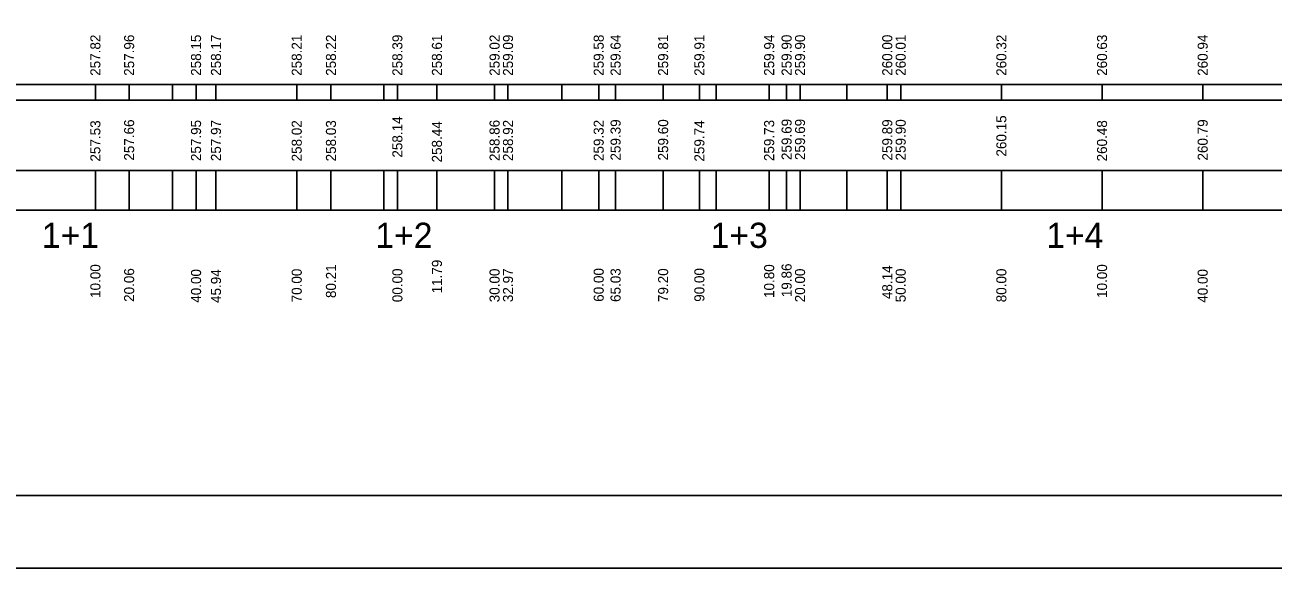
# Model space of a CAD drawing. Extents: x -550605 to -538780, y -1102367 to -1093705.
# Drawn here: x -540305.8 to -539933.8, y -1097677.3 to -1097515.5 of the extents above; entities that cross this region are included whole.
import ezdxf

# ---------------------------------------------------------------- set-up
doc = ezdxf.new("R2010")
doc.units = 0
for name, color, linetype in [('PP - kóty', 7, 'Continuous'), ('PP - popis', 7, 'Continuous'), ('Vrstva 57 - Ohrada pro tisk', 7, 'Continuous')]:
    doc.layers.add(name, color=color, linetype=linetype)

msp = doc.modelspace()

# ---------------------------------------------------------------- linework, layer by layer
at = {"layer": 'PP - popis'}
for p, q in [((-540261.8, -1097533.29), (-540261.8, -1097537.91)), ((-540261.8, -1097533.29), (-540261.8, -1097537.91)), ((-540198.8, -1097533.29), (-540198.8, -1097537.91)), ((-540198.8, -1097533.29), (-540198.8, -1097537.91)), ((-540145.8, -1097533.29), (-540145.8, -1097537.91)), ((-540145.8, -1097533.29), (-540145.8, -1097537.91)), ((-540099.8, -1097533.29), (-540099.8, -1097537.91)), ((-540099.8, -1097533.29), (-540099.8, -1097537.91)), ((-540060.8, -1097533.29), (-540060.8, -1097537.91)), ((-540060.8, -1097533.29), (-540060.8, -1097537.91)), ((-540261.8, -1097558.89), (-540261.8, -1097570.66)), ((-540261.8, -1097558.89), (-540261.8, -1097570.66)), ((-540198.8, -1097558.89), (-540198.8, -1097570.66)), ((-540198.8, -1097558.89), (-540198.8, -1097570.66)), ((-540145.8, -1097558.89), (-540145.8, -1097570.66)), ((-540145.8, -1097558.89), (-540145.8, -1097570.66)), ((-540099.8, -1097558.89), (-540099.8, -1097570.66)), ((-540099.8, -1097558.89), (-540099.8, -1097570.66)), ((-540060.8, -1097558.89), (-540060.8, -1097570.66)), ((-540060.8, -1097558.89), (-540060.8, -1097570.66)), ((-541394.8, -1097570.66), (-539200.8, -1097570.66))]:
    msp.add_line(p, q, dxfattribs=at)
for points in [[(-540284.8, -1097533.29), (-540284.8, -1097537.91)], [(-540274.74, -1097533.29), (-540274.74, -1097537.91)], [(-540254.8, -1097533.29), (-540254.8, -1097537.91)], [(-540248.86, -1097533.29), (-540248.86, -1097537.91)], [(-540224.8, -1097533.29), (-540224.8, -1097537.91)], [(-540214.59, -1097533.29), (-540214.59, -1097537.91)], [(-540194.8, -1097533.29), (-540194.8, -1097537.91)], [(-540183.01, -1097533.29), (-540183.01, -1097537.91)], [(-540165.83, -1097533.29), (-540165.83, -1097537.91)], [(-540161.83, -1097533.29), (-540161.83, -1097537.91)], [(-540134.8, -1097533.29), (-540134.8, -1097537.91)], [(-540129.77, -1097533.29), (-540129.77, -1097537.91)], [(-540115.6, -1097533.29), (-540115.6, -1097537.91)], [(-540104.8, -1097533.29), (-540104.8, -1097537.91)], [(-540084, -1097533.29), (-540084, -1097537.91)], [(-540078.8, -1097533.29), (-540078.8, -1097537.91)], [(-540074.8, -1097533.29), (-540074.8, -1097537.91)], [(-540048.8, -1097533.29), (-540048.8, -1097537.91)], [(-540044.8, -1097533.29), (-540044.8, -1097537.91)], [(-540014.8, -1097533.29), (-540014.8, -1097537.91)], [(-539984.8, -1097533.29), (-539984.8, -1097537.91)], [(-539954.8, -1097533.29), (-539954.8, -1097537.91)], [(-540284.8, -1097558.89), (-540284.8, -1097570.66)], [(-540274.74, -1097558.89), (-540274.74, -1097570.66)], [(-540254.8, -1097558.89), (-540254.8, -1097570.66)], [(-540248.86, -1097558.89), (-540248.86, -1097570.66)], [(-540224.8, -1097558.89), (-540224.8, -1097570.66)], [(-540214.59, -1097558.89), (-540214.59, -1097570.66)], [(-540194.8, -1097558.89), (-540194.8, -1097570.66)], [(-540183.01, -1097558.89), (-540183.01, -1097570.66)], [(-540165.83, -1097558.89), (-540165.83, -1097570.66)], [(-540161.83, -1097558.89), (-540161.83, -1097570.66)], [(-540134.8, -1097558.89), (-540134.8, -1097570.66)], [(-540129.77, -1097558.89), (-540129.77, -1097570.66)], [(-540115.6, -1097558.89), (-540115.6, -1097570.66)], [(-540104.8, -1097558.89), (-540104.8, -1097570.66)], [(-540084, -1097558.89), (-540084, -1097570.66)], [(-540078.8, -1097558.89), (-540078.8, -1097570.66)], [(-540074.8, -1097558.89), (-540074.8, -1097570.66)], [(-540048.8, -1097558.89), (-540048.8, -1097570.66)], [(-540044.8, -1097558.89), (-540044.8, -1097570.66)], [(-540014.8, -1097558.89), (-540014.8, -1097570.66)], [(-539984.8, -1097558.89), (-539984.8, -1097570.66)], [(-539954.8, -1097558.89), (-539954.8, -1097570.66)], [(-541394.8, -1097655.66), (-541347.44, -1097655.66), (-541347.44, -1097667.66), (-541325.3, -1097667.66), (-541325.3, -1097655.66), (-541196.07, -1097655.66), (-541196.07, -1097667.66), (-541142.23, -1097667.66), (-541142.23, -1097655.66), (-540615.98, -1097655.66), (-540615.98, -1097643.66), (-540580.64, -1097643.66), (-540580.64, -1097655.66), (-540387.05, -1097655.66), (-540387.05, -1097643.66), (-540360.85, -1097643.66), (-540360.85, -1097655.66), (-539200.59, -1097655.66)]]:
    msp.add_lwpolyline(points, dxfattribs=at)
at = {"layer": 'Vrstva 57 - Ohrada pro tisk'}
for points in [[(-541634.97, -1097677.25), (-538779.82, -1097677.25), (-538779.81, -1097107.25), (-541634.97, -1097107.25)], [(-541392.34, -1097533.29), (-539148.29, -1097533.29), (-539148.29, -1097512.53), (-541392.34, -1097512.53)], [(-541392.09, -1097558.89), (-539148.83, -1097558.89), (-539148.83, -1097537.91), (-541392.09, -1097537.91)]]:
    msp.add_lwpolyline(points, close=True, dxfattribs=at)

# ---------------------------------------------------------------- texts
at = {"layer": 'PP - kóty'}
for s, p in [('257.82', (-540283.3, -1097530.66)), ('257.96', (-540273.24, -1097530.66)), ('258.15', (-540253.3, -1097530.66)), ('258.17', (-540247.36, -1097530.66)), ('258.21', (-540223.3, -1097530.66)), ('258.22', (-540213.09, -1097530.66)), ('258.39', (-540193.3, -1097530.66)), ('258.61', (-540181.51, -1097530.66)), ('259.02', (-540164.33, -1097530.66)), ('259.09', (-540160.33, -1097530.66)), ('259.58', (-540133.3, -1097530.66)), ('259.64', (-540128.27, -1097530.66)), ('259.81', (-540114.1, -1097530.66)), ('259.91', (-540103.3, -1097530.66)), ('259.94', (-540082.5, -1097530.66)), ('259.90', (-540077.3, -1097530.66)), ('259.90', (-540073.3, -1097530.66)), ('260.00', (-540047.3, -1097530.66)), ('260.01', (-540043.3, -1097530.66)), ('260.32', (-540013.3, -1097530.66)), ('260.63', (-539983.3, -1097530.66)), ('260.94', (-539953.3, -1097530.66)), ('257.53', (-540283.3, -1097556.2)), ('257.66', (-540273.24, -1097555.92)), ('257.95', (-540253.3, -1097556.06)), ('257.97', (-540247.36, -1097556.08)), ('258.02', (-540223.3, -1097556.15)), ('258.03', (-540213.09, -1097556.15)), ('258.14', (-540193.3, -1097555.02)), ('258.44', (-540181.51, -1097556.46)), ('258.86', (-540164.33, -1097556.04)), ('258.92', (-540160.33, -1097556.04)), ('259.32', (-540133.3, -1097556.04)), ('259.39', (-540128.27, -1097555.89)), ('259.60', (-540114.1, -1097555.87)), ('259.74', (-540103.3, -1097556.2)), ('259.73', (-540082.5, -1097556.06)), ('259.69', (-540077.3, -1097555.75)), ('259.69', (-540073.3, -1097555.75)), ('259.89', (-540047.3, -1097555.89)), ('259.90', (-540043.3, -1097555.87)), ('260.15', (-540013.3, -1097554.71)), ('260.48', (-539983.3, -1097556.15)), ('260.79', (-539953.3, -1097555.89))]:
    msp.add_text(s, height=3, rotation=90, dxfattribs=at).set_placement(p)
at = {"layer": 'PP - popis'}
for s, p in [('1+1', (-540300.73, -1097581.91)), ('1+2', (-540201.35, -1097581.91)), ('1+3', (-540101.42, -1097581.91)), ('1+4', (-540001.39, -1097581.91))]:
    msp.add_text(s, height=7.5, dxfattribs=at).set_placement(p)
for s, p in [('10.00', (-540283.3, -1097596.81)), ('20.06', (-540273.24, -1097597.99)), ('40.00', (-540253.3, -1097598.25)), ('45.94', (-540247.36, -1097598.32)), ('70.00', (-540223.3, -1097598.13)), ('80.21', (-540213.09, -1097596.85)), ('00.00', (-540193.3, -1097598.08)), ('11.79', (-540181.51, -1097595.46)), ('30.00', (-540164.33, -1097598.11)), ('32.97', (-540160.33, -1097598.06)), ('60.00', (-540133.3, -1097597.96)), ('65.03', (-540128.27, -1097598.01)), ('79.20', (-540114.1, -1097598.04)), ('90.00', (-540103.3, -1097597.96)), ('10.80', (-540082.5, -1097596.83)), ('19.86', (-540077.3, -1097596.59)), ('20.00', (-540073.3, -1097598.11)), ('48.14', (-540047.3, -1097597.16)), ('50.00', (-540043.3, -1097598.11)), ('80.00', (-540013.3, -1097598.11)), ('10.00', (-539983.3, -1097596.81)), ('40.00', (-539953.3, -1097598.25))]:
    msp.add_text(s, height=3, rotation=90, dxfattribs=at).set_placement(p)

doc.saveas('drawing.dxf')
